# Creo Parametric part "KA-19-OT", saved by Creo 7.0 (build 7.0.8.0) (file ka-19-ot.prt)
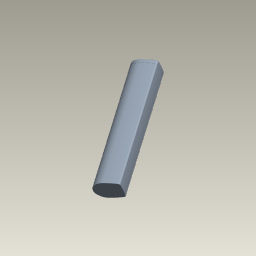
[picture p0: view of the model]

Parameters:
  PTC_COMMON_NAME = "ka-19-ot.prt"
  PTC_WM_REVISION = "A"
  PTC_WM_ITERATION = "1"
  PTC_WM_VERSION = "A.1"
  PTC_WM_LIFECYCLE_STATE = "Concept"
  PTC_WM_LIFECYCLE = "Life Cycle Schema Type 1"
  PTC_WM_LOCATION = "/Products/KA19_CN2215/CAD"
  PTC_WM_CREATED_BY = "Jörg Monien"
  PTC_WM_CREATED_ON = "2026-08-11"
  PTC_WM_MODIFIED_BY = "Jörg Monien"
  PTC_WM_MODIFIED_ON = "2026-08-11"
  PTC_WM_NAME = "ka-19-ot.prt"
  PTC_WM_NUMBER = "KA-19-OT.PRT"
  PDMREV = "A.1+"
  PDMRL = "Concept"
  PROI_REVISION = "A"
  PROI_VERSION = "1"
  PROI_RELEASE = "Concept"

Created from: 1079W4001-OT.PRT

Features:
  1. datum plane "RIGHT"
  2. datum plane "TOP"
  3. datum plane "FRONT"
  4. coordinate system
  5. datum axis
  6. datum axis
  7. datum axis
  8. imported feature
  9. extrusion "Extrude 1"

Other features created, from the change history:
  component interface "Component Interface id 13859"
  patch "Solidify 1" (2 times)
  extrusion "Extrude 4" (2 times)
  extrusion "Extrude 1" (2 times)
  datum plane "DTM1"
  extrusion "Extrude 2"
  extruded cut "Extrude 3"
  feature "Body Merge 1"
  extrusion "Extrude 3"
  feature "Copy Geometry id 16659"
  feature "Copy Geometry id 16744"
  feature "Copy Geometry id 16829"
  feature "Copy Geometry id 16914"
  feature "Copy Geometry id 16999"
  patch "Solidify 2"
  patch "Solidify 3"
  patch "Solidify 4"

Other named items: X-AXES, Y-AXES, Z-AXES, CS0

Layers: ANNOTATIONS, AXES, COSMETICS, CSYS, CURVES, EXT_COPY_GEOM, PLANES, POINTS, PUBLISHED_GEOM, QUILTS, SOLIDS, STARTUP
